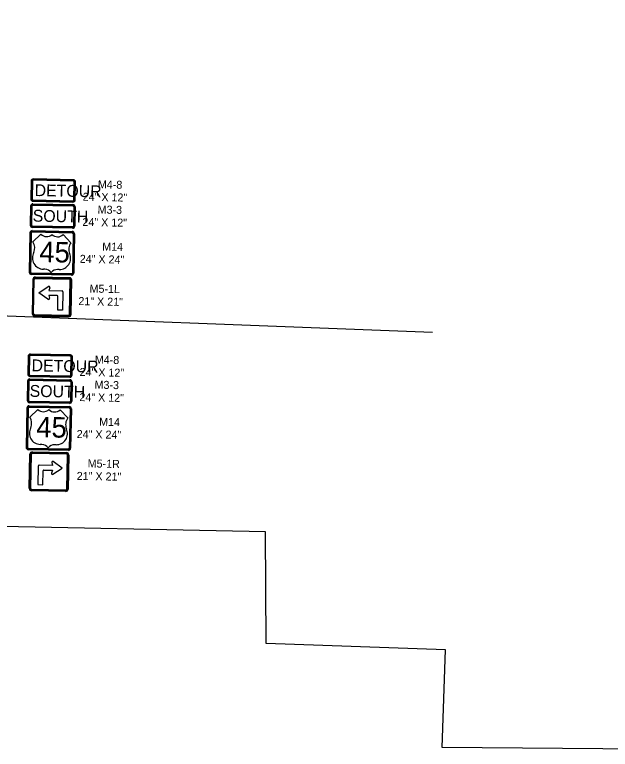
# Model space of a CAD drawing. Extents: x 331323 to 388339, y 121519 to 205315.
# Drawn here: x 375372 to 379389, y 129131 to 134083 of the extents above; entities that cross this region are included whole.
import ezdxf

# ---------------------------------------------------------------- set-up
doc = ezdxf.new("R2010")
doc.units = 0
for name, color, linetype in [('Level 21', 7, 'Continuous'), ('Level 57', 7, 'Continuous'), ('P_SGN_Cell', 7, 'Continuous')]:
    doc.layers.add(name, color=color, linetype=linetype)

msp = doc.modelspace()

# ---------------------------------------------------------------- linework, layer by layer
at = {"layer": 'Level 21'}
msp.add_lwpolyline([(387110, 131789), (379629.8, 131947), (379608.6, 129130.6), (378253.9, 129142.3), (378276.4, 129801.4), (377067.3, 129844.4), (377063.5, 130597.8), (375063.3, 130636.2), (375076, 132102.1), (370942.7, 132184.5)], dxfattribs=at)
at = {"layer": 'Level 57'}
msp.add_lwpolyline([(371829.2, 134082.8), (371920.6, 134048.7), (372916.1, 133481.3), (373487.9, 133084.4), (374440.1, 132334.1), (374796.3, 132072.6), (378189.4, 131941.9)], dxfattribs=at)
at = {"layer": 'P_SGN_Cell'}
for p, q in [((375479.7, 132793.7), (375477.1, 132663.7)), ((375483.5, 132793.6), (375480.9, 132663.6)), ((375488.5, 132793.5), (375485.9, 132663.5)), ((375494.8, 132808.4), (375765, 132802.9)), ((375494.9, 132799.6), (375764.8, 132794.2)), ((375495, 132804.6), (375764.9, 132799.2)), ((375770.9, 132787.8), (375768.3, 132657.8)), ((375775.9, 132787.7), (375773.3, 132657.7)), ((375779.7, 132787.6), (375777.1, 132657.6)), ((375490.3, 132627.2), (375760.4, 132621.8)), ((375490.4, 132623.4), (375760.3, 132618)), ((375761.8, 132642.9), (375491.8, 132648.4)), ((375761.8, 132646.7), (375491.9, 132652.1)), ((375761.9, 132651.7), (375492, 132657.1)), ((375475.2, 132612.5), (375469.8, 132346.8)), ((375478.9, 132612.4), (375473.6, 132346.7)), ((375483.9, 132612.3), (375478.6, 132346.6)), ((375490.3, 132618.5), (375760.2, 132613)), ((375493.9, 132550.7), (375548.6, 132603.1)), ((375533.8, 132615.8), (375533.8, 132615.8)), ((375698.6, 132600.1), (375751.1, 132545.5)), ((375766.4, 132606.6), (375761, 132340.9)), ((375771.4, 132606.5), (375766, 132340.8)), ((375775.1, 132606.5), (375769.8, 132340.7)), ((375754.5, 132326), (375484.5, 132331.5)), ((375754.5, 132329.8), (375484.6, 132335.2)), ((375754.6, 132334.8), (375484.7, 132340.2)), ((375576, 132366.8), (375565.3, 132367)), ((375672.4, 132364.9), (375661.7, 132365.1)), ((375494.5, 132298), (375489.9, 132068.4)), ((375494.3, 132068.3), (375498.9, 132297.9)), ((375499.8, 132068.2), (375504.4, 132297.8)), ((375511.1, 132304.2), (375740.7, 132299.6)), ((375511.2, 132309.7), (375740.8, 132305.1)), ((375740.9, 132309.5), (375511.3, 132314.1)), ((375742.5, 132063.3), (375747.1, 132292.9)), ((375748, 132063.2), (375752.6, 132292.8)), ((375752.4, 132063.1), (375757, 132292.7)), ((375535.4, 132208.6), (375598.2, 132249.9)), ((375608, 132242.4), (375601.9, 132223.6)), ((375601.9, 132223.6), (375691, 132221.8)), ((375596.4, 132164.7), (375535.4, 132208.6)), ((375658.6, 132189.7), (375601.3, 132190.8)), ((375601.3, 132190.8), (375606.6, 132171.8)), ((375662.1, 132091.2), (375664, 132184.1)), ((375697.4, 132215.2), (375694.9, 132090.5)), ((375694.9, 132090.5), (375662.1, 132091.2)), ((375506, 132051.6), (375735.6, 132047)), ((375506.1, 132056), (375735.7, 132051.4)), ((375506.2, 132061.5), (375735.8, 132056.8)), ((375459.1, 131612.7), (375456.5, 131482.7)), ((375462.8, 131612.6), (375460.2, 131482.6)), ((375467.8, 131612.5), (375465.2, 131482.5)), ((375474.2, 131627.4), (375744.3, 131621.9)), ((375474.2, 131618.6), (375744.2, 131613.2)), ((375474.3, 131623.6), (375744.3, 131618.2)), ((375750.3, 131606.8), (375747.7, 131476.8)), ((375755.3, 131606.7), (375752.7, 131476.7)), ((375759, 131606.6), (375756.4, 131476.7)), ((375454.5, 131431.5), (375449.2, 131165.8)), ((375458.3, 131431.5), (375452.9, 131165.7)), ((375463.3, 131431.4), (375457.9, 131165.6)), ((375469.6, 131446.2), (375739.7, 131440.8)), ((375469.6, 131437.5), (375739.6, 131432)), ((375469.7, 131442.5), (375739.7, 131437)), ((375741.2, 131465.7), (375471.2, 131471.2)), ((375741.1, 131462), (375471.2, 131467.4)), ((375741.3, 131470.7), (375471.3, 131476.2)), ((375513.2, 131434.9), (375513.2, 131434.9)), ((375473.3, 131369.7), (375527.9, 131422.2)), ((375677.9, 131419.1), (375730.4, 131364.5)), ((375745.7, 131425.7), (375740.3, 131159.9)), ((375750.7, 131425.6), (375745.3, 131159.8)), ((375754.4, 131425.5), (375749.1, 131159.8)), ((375555.3, 131185.8), (375544.6, 131186)), ((375651.7, 131183.9), (375641, 131184.1)), ((375733.8, 131145.1), (375463.8, 131150.5)), ((375733.9, 131148.8), (375463.9, 131154.2)), ((375734, 131153.8), (375464, 131159.2)), ((375491.3, 131135.7), (375721, 131131)), ((375470, 130890), (375474.6, 131119.6)), ((375474.3, 130889.9), (375479, 131119.5)), ((375479.8, 130889.8), (375484.4, 131119.4)), ((375720.8, 131121.2), (375491.1, 131125.8)), ((375720.9, 131126.7), (375491.2, 131131.3)), ((375722.6, 130884.9), (375727.2, 131114.5)), ((375728, 130884.8), (375732.7, 131114.4)), ((375737, 131114.3), (375732.4, 130884.7)), ((375531, 131039.7), (375528.5, 130915)), ((375626.8, 131044.3), (375537.7, 131046.1)), ((375621.4, 131063.3), (375626.8, 131044.3)), ((375692.6, 131026.6), (375631.6, 131070.4)), ((375561.3, 130914.4), (375563.1, 131007.3)), ((375568.7, 131012.7), (375626.1, 131011.5)), ((375626.1, 131011.5), (375620, 130992.8)), ((375629.9, 130985.3), (375692.6, 131026.6)), ((375528.5, 130915), (375561.3, 130914.4)), ((375715.7, 130868.6), (375486, 130873.2)), ((375715.8, 130873), (375486.1, 130877.6)), ((375715.9, 130878.4), (375486.2, 130883.1))]:
    msp.add_line(p, q, dxfattribs=at)
for points in [[(375767.9, 132961.3), (375498, 132966.7)], [(375768, 132966.3), (375498.1, 132971.7)], [(375768.1, 132970.1), (375498.2, 132975.5)], [(375482.9, 132960.8), (375480.5, 132840.8)], [(375486.6, 132960.7), (375484.2, 132840.7)], [(375491.6, 132960.6), (375489.2, 132840.6)], [(375771.6, 132835), (375774.1, 132954.9)], [(375776.6, 132834.9), (375779.1, 132954.8)], [(375780.4, 132834.8), (375782.8, 132954.8)], [(375495.1, 132825.5), (375765.1, 132820.1)], [(375495.2, 132829.3), (375765.2, 132823.8)], [(375495.3, 132834.3), (375765.3, 132828.8)], [(375462.2, 131779.8), (375459.8, 131659.8)], [(375466, 131779.7), (375463.5, 131659.8)], [(375471, 131779.6), (375468.5, 131659.7)], [(375747.3, 131780.3), (375477.3, 131785.8)], [(375747.4, 131785.3), (375477.4, 131790.8)], [(375747.4, 131789.1), (375477.5, 131794.5)], [(375751, 131654), (375753.4, 131774)], [(375756, 131653.9), (375758.4, 131773.9)], [(375759.7, 131653.8), (375762.1, 131773.8)], [(375474.5, 131644.5), (375744.4, 131639.1)], [(375474.6, 131648.3), (375744.5, 131642.9)], [(375474.7, 131653.3), (375744.6, 131647.9)]]:
    msp.add_lwpolyline(points, dxfattribs=at)
for centre, radius, start, end in [((375497.9, 132960.5), 15, 88.8468, 178.8468), ((375497.9, 132960.5), 11.2, 88.8468, 178.8468), ((375497.9, 132960.5), 6.25, 88.8468, 178.8468), ((375497.9, 132960.5), 6.25, 88.8468, 96.1883), ((375767.8, 132955.1), 11.2, 358.8468, 88.8468), ((375767.8, 132955.1), 15, 358.8468, 88.8468), ((375767.8, 132955.1), 6.25, 358.8468, 88.8468), ((375495.5, 132840.5), 15, 178.8468, 268.8468), ((375495.5, 132840.5), 11.2, 178.8468, 268.8468), ((375495.5, 132840.5), 6.25, 178.8468, 268.8468), ((375765.4, 132835.1), 15, 268.8468, 358.8468), ((375765.4, 132835.1), 11.2, 268.8468, 358.8468), ((375765.4, 132835.1), 6.25, 268.8468, 358.8468), ((375494.7, 132793.4), 15, 89.6119, 178.8462), ((375494.7, 132793.4), 11.2, 88.8462, 178.8462), ((375494.7, 132793.4), 6.25, 88.8462, 178.8462), ((375764.7, 132787.9), 6.25, 358.8462, 88.8462), ((375764.7, 132787.9), 11.2, 358.8462, 88.8462), ((375764.7, 132787.9), 15, 358.8462, 88.8462), ((375490.2, 132612.2), 15, 89.6119, 178.8462), ((375492.1, 132663.4), 15, 178.8462, 268.8462), ((375490.2, 132612.2), 11.2, 88.8462, 178.8462), ((375492.1, 132663.4), 11.2, 178.8462, 268.8462), ((375492.1, 132663.4), 6.25, 178.8462, 268.8462), ((375760.1, 132606.8), 15, 358.8462, 88.8462), ((375762.1, 132657.9), 11.2, 268.8462, 358.8462), ((375762.1, 132657.9), 15, 268.8462, 358.8462), ((375762.1, 132657.9), 6.25, 268.8462, 358.8462), ((375490.2, 132612.2), 6.25, 88.8462, 178.8462), ((375586.9, 132640.6), 53.6, 224.4191, 313.2734), ((375661.8, 132639.1), 53.6, 224.4191, 313.2734), ((375760.1, 132606.8), 6.25, 358.8462, 88.8462), ((375760.1, 132606.8), 11.2, 358.8462, 88.8462), ((375432.3, 132507.8), 75, 337.7159, 34.7982), ((375811.1, 132500.5), 75, 143.1143, 201.9873), ((375566.8, 132442), 75, 150.0981, 268.8463), ((375673.9, 132439.9), 75, 268.8462, 25.6928), ((375484.8, 132346.5), 15, 178.8462, 268.8462), ((375484.8, 132346.5), 11.2, 178.8462, 268.8462), ((375484.8, 132346.5), 6.25, 178.8462, 268.8462), ((375574.6, 132312.6), 54.2, 36.0584, 88.5039), ((375660.9, 132310.9), 54.2, 89.1885, 141.634), ((375754.8, 132341), 11.2, 268.8462, 358.8462), ((375754.8, 132341), 15, 268.8462, 358.8462), ((375754.8, 132341), 6.25, 268.8462, 358.8462), ((375510.9, 132297.7), 16.4, 88.8462, 178.8462), ((375510.9, 132297.7), 12, 88.8462, 178.8462), ((375510.9, 132297.7), 6.56, 88.8462, 178.8462), ((375740.6, 132293.1), 6.56, 358.8462, 88.8462), ((375740.6, 132293.1), 12, 358.8462, 88.8462), ((375740.6, 132293.1), 16.4, 358.8462, 88.8462), ((375601.8, 132244.4), 6.56, 342.0436, 123.3759), ((375658.5, 132184.2), 5.47, 358.8462, 88.8462), ((375690.9, 132215.3), 6.56, 358.8462, 88.8462), ((375600.3, 132170.1), 6.56, 234.3166, 15.6488), ((375506.3, 132068), 16.4, 178.8462, 268.8462), ((375506.3, 132068), 12, 178.8462, 268.8462), ((375506.3, 132068), 6.56, 178.8462, 268.8462), ((375736, 132063.4), 16.4, 268.8462, 358.8462), ((375736, 132063.4), 12, 268.8462, 358.8462), ((375736, 132063.4), 6.56, 268.8462, 358.8462), ((375477.2, 131779.5), 15, 88.8468, 178.8468), ((375477.2, 131779.5), 11.2, 88.8468, 178.8468), ((375477.2, 131779.5), 6.25, 88.8468, 178.8468), ((375477.2, 131779.5), 6.25, 88.8468, 96.1883), ((375747.1, 131774.1), 6.25, 358.8468, 88.8468), ((375747.1, 131774.1), 15, 358.8468, 88.8468), ((375747.1, 131774.1), 11.2, 358.8468, 88.8468), ((375474.8, 131659.5), 15, 178.8468, 268.8468), ((375474.8, 131659.5), 11.2, 178.8468, 268.8468), ((375474.8, 131659.5), 6.25, 178.8468, 268.8468), ((375744.7, 131654.1), 15, 268.8468, 358.8468), ((375744.7, 131654.1), 11.2, 268.8468, 358.8468), ((375744.7, 131654.1), 6.25, 268.8468, 358.8468), ((375474.1, 131612.4), 15, 89.6119, 178.8462), ((375474.1, 131612.4), 11.2, 88.8462, 178.8462), ((375474.1, 131612.4), 6.25, 88.8462, 178.8462), ((375744, 131606.9), 6.25, 358.8462, 88.8462), ((375744, 131606.9), 15, 358.8462, 88.8462), ((375744, 131606.9), 11.2, 358.8462, 88.8462), ((375471.5, 131482.4), 15, 178.8462, 268.8462), ((375471.5, 131482.4), 11.2, 178.8462, 268.8462), ((375471.5, 131482.4), 6.25, 178.8462, 268.8462), ((375469.5, 131431.2), 15, 89.6119, 178.8462), ((375469.5, 131431.2), 11.2, 88.8462, 178.8462), ((375469.5, 131431.2), 6.25, 88.8462, 178.8462), ((375739.4, 131425.8), 6.25, 358.8462, 88.8462), ((375739.4, 131425.8), 15, 358.8462, 88.8462), ((375739.4, 131425.8), 11.2, 358.8462, 88.8462), ((375741.4, 131477), 15, 268.8462, 358.8462), ((375741.4, 131477), 11.2, 268.8462, 358.8462), ((375741.4, 131477), 6.25, 268.8462, 358.8462), ((375566.2, 131459.7), 53.6, 224.4191, 313.2734), ((375641.2, 131458.2), 53.6, 224.4191, 313.2734), ((375411.7, 131326.9), 75, 337.7159, 34.7982), ((375790.4, 131319.5), 75, 143.1143, 201.9873), ((375546.1, 131261), 75, 150.0981, 268.8463), ((375653.2, 131258.9), 75, 268.8462, 25.6928), ((375553.9, 131131.6), 54.2, 36.0584, 88.5039), ((375640.3, 131129.9), 54.2, 89.1885, 141.634), ((375464.1, 131165.5), 15, 178.8462, 268.8462), ((375464.1, 131165.5), 11.2, 178.8462, 268.8462), ((375464.1, 131165.5), 6.25, 178.8462, 268.8462), ((375491, 131119.3), 16.4, 88.8462, 178.8462), ((375734.1, 131160.1), 15, 268.8462, 358.8462), ((375734.1, 131160.1), 11.2, 268.8462, 358.8462), ((375734.1, 131160.1), 6.25, 268.8462, 358.8462), ((375491, 131119.3), 12, 88.8462, 178.8462), ((375491, 131119.3), 6.56, 88.8462, 178.8462), ((375720.6, 131114.6), 6.56, 358.8462, 88.8462), ((375720.6, 131114.6), 12, 358.8462, 88.8462), ((375720.6, 131114.6), 16.4, 358.8462, 88.8462), ((375537.5, 131039.6), 6.56, 88.8462, 178.8462), ((375627.8, 131065.1), 6.56, 54.3166, 195.6488), ((375568.6, 131007.2), 5.47, 88.8462, 178.8462), ((375626.3, 130990.7), 6.56, 162.0436, 303.3759), ((375486.4, 130889.6), 16.4, 178.8462, 268.8462), ((375486.4, 130889.6), 12, 178.8462, 268.8462), ((375486.4, 130889.6), 6.56, 178.8462, 268.8462), ((375716, 130885), 16.4, 268.8462, 358.8462), ((375716, 130885), 12, 268.8462, 358.8462), ((375716, 130885), 6.56, 268.8462, 358.8462)]:
    msp.add_arc(centre, radius, start, end, dxfattribs=at)

# ---------------------------------------------------------------- texts
for s, height, rotation, p in [('M4-8', 54, 358.8468, (375932.5, 132912.4)), ('DETOUR', 80, 358.8468, (375505.9, 132860.1)), ('24" X 12"', 54, 358.8468, (375830.2, 132828.7)), ('SOUTH', 80, 358.8462, (375492.9, 132688.2)), ('M3-3', 54, 358.8462, (375930.9, 132742.7)), ('24" X 12"', 54, 358.8462, (375828.6, 132659.1)), ('45', 138, 358.8462, (375537.3, 132415.9)), ('M14', 54, 358.8462, (375961.8, 132493)), ('24" X 24"', 54, 358.8462, (375810.3, 132410.3)), ('M5-1L', 54, 358.8462, (375876.5, 132209.8)), ('21" X 21"', 54, 358.8462, (375801.1, 132125.5)), ('M4-8', 54, 358.8468, (375911.8, 131731.4)), ('DETOUR', 80, 358.8468, (375485.3, 131679.2)), ('24" X 12"', 54, 358.8468, (375809.5, 131647.7)), ('SOUTH', 80, 358.8462, (375472.2, 131507.2)), ('M3-3', 54, 358.8462, (375910.2, 131561.8)), ('24" X 12"', 54, 358.8462, (375807.9, 131478.1)), ('45', 138, 358.8462, (375516.6, 131235)), ('M14', 54, 358.8462, (375941.1, 131312)), ('24" X 24"', 54, 358.8462, (375789.7, 131229.3)), ('M5-1R', 54, 358.8462, (375863.8, 131031.2)), ('21" X 21"', 54, 358.8462, (375790.1, 130947))]:
    msp.add_text(s, height=height, rotation=rotation, dxfattribs=at).set_placement(p)

doc.saveas('drawing.dxf')
